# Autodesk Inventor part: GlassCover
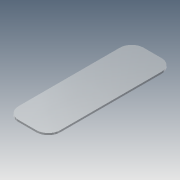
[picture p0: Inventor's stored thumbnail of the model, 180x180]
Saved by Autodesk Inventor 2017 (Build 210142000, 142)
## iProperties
Created: 2019-02
Part Number: GlassCover
Material: Glass
Document SubType Name: Modeling
Designer: user
Density: 2.18 g/cm^3
Appearance: Clear
Author: user
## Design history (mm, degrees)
sketch "Sketch1"
  geometry: L1 (31.297, 218.537)-(31.297, 50.515) reference; L2 (42.989, 38.823)-(71.011, 38.823) reference; L3 (82.703, 50.515)-(82.703, 218.537) reference; L4 (71.011, 230.23)-(42.989, 230.23) reference; L5 (72, 29.526)-(42, 29.526) reference; L6 (22, 49.526)-(22, 219.526) reference; L7 (42, 239.526)-(72, 239.526) reference; L8 (92, 219.526)-(92, 49.526) reference; A1 r 20 centre (42, 49.526) between (22, 49.526) and (42, 29.526) reference; A2 r 20 centre (42, 219.526) between (42, 239.526) and (22, 219.526) reference; A3 r 20 centre (72, 219.526) between (92, 219.526) and (72, 239.526) reference; A4 r 20 centre (72, 49.526) between (72, 29.526) and (92, 49.526) reference; 1 further point
  constraints: 16 end point, 8 point on circle, 4 centre point, 4 horizontal, 4 vertical, 32 other
extrude "Extrusion1" new body sketch "Sketch1" distance "d0" = 3; taper "d1" = 0 deg
body "Solid1"
